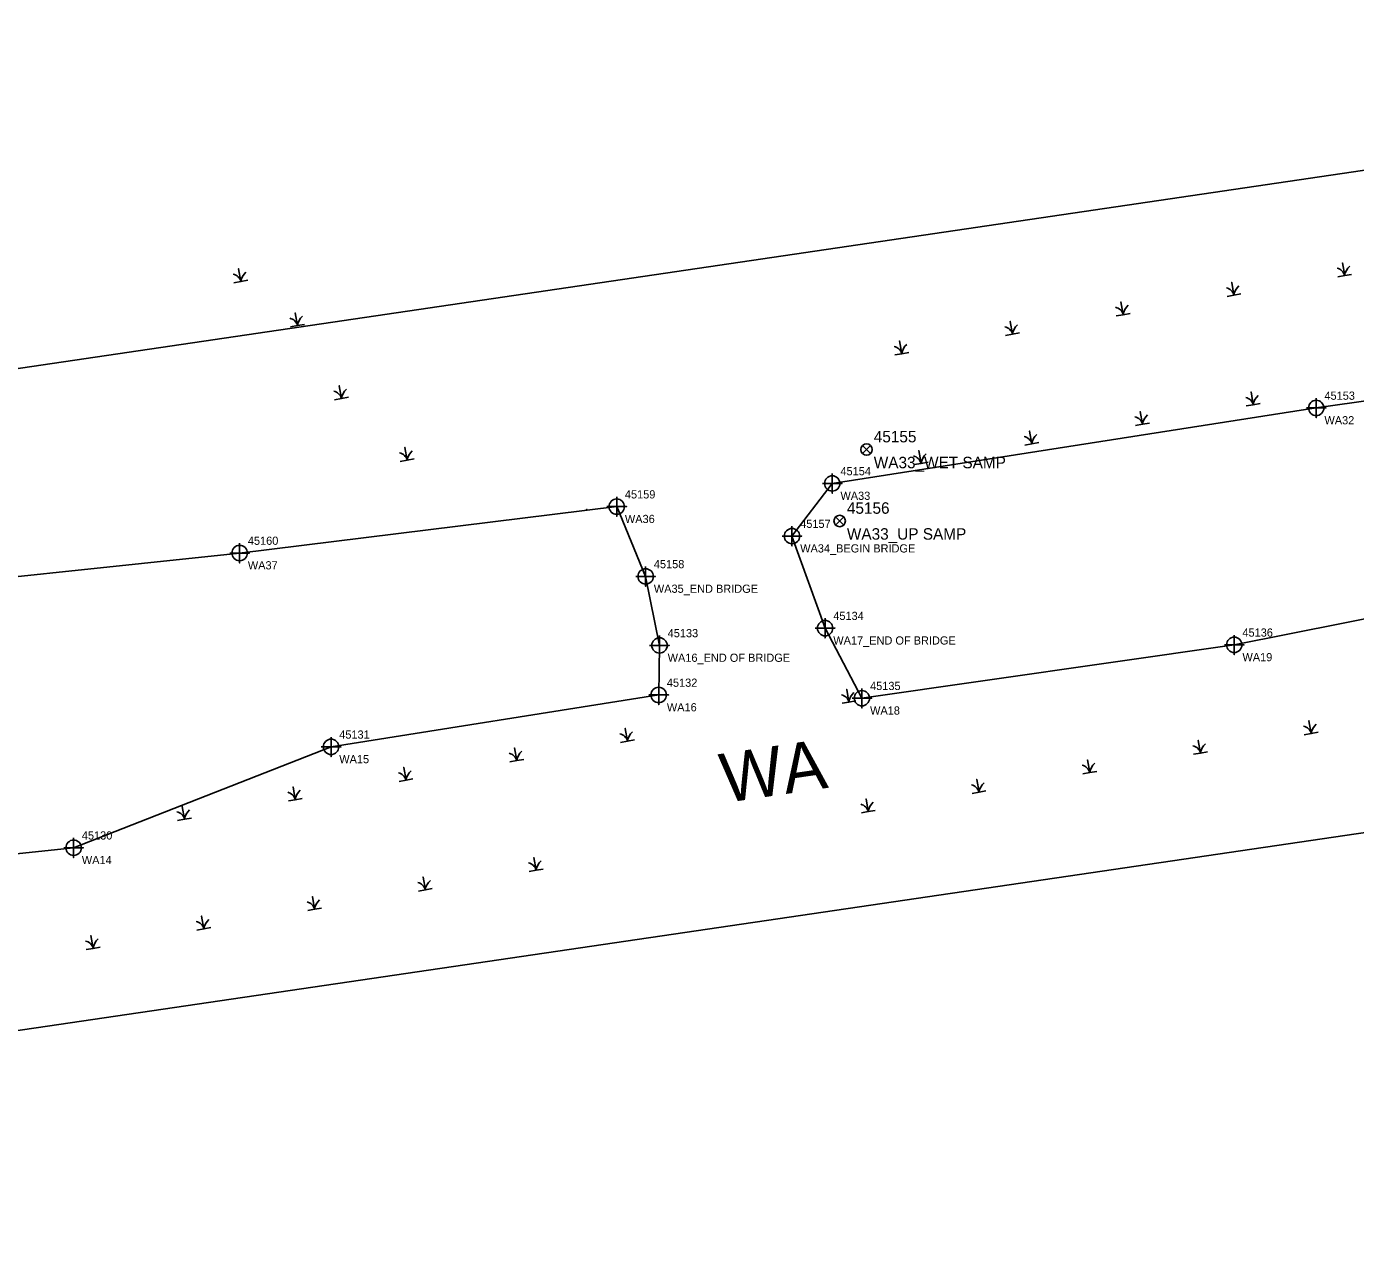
# Model space of a CAD drawing. Extents: x 2111078 to 2112659, y 581517 to 581899.
# Drawn here: x 2111863.2 to 2112268.6, y 581523.2 to 581899.2 of the extents above; entities that cross this region are included whole.
import ezdxf

# ---------------------------------------------------------------- set-up
doc = ezdxf.new("R2010")
doc.units = 0
for name, color, linetype in [('Default', 7, 'Continuous'), ('Exist Environmental Wetland Boundary', 7, 'Continuous'), ('Exist Environmental Wetland Boundary Cogo Comment', 7, 'Continuous'), ('Exist Environmental Wetland Boundary Cogo Number', 7, 'Continuous'), ('Exist Environmental Wetland Boundary Cogo Point CELL', 7, 'Continuous'), ('Exist Environmental Wetland Boundary Text', 7, 'Continuous'), ('Exist Hydro Swamp or Marsh', 7, 'Continuous')]:
    doc.layers.add(name, color=color, linetype=linetype)

msp = doc.modelspace()

# ---------------------------------------------------------------- linework, layer by layer
at = {"layer": 'Default'}
for p, q in [((2112120.71, 581771.41), (2112118.24, 581768.93)), ((2112118.24, 581771.41), (2112120.71, 581768.93)), ((2112112.51, 581749.62), (2112110.03, 581747.15)), ((2112110.03, 581749.62), (2112112.51, 581747.15))]:
    msp.add_line(p, q, dxfattribs=at)
msp.add_lwpolyline([(2111089.87, 581523.16), (2111077.52, 581722.78), (2111579.66, 581753.48), (2112568.99, 581899.18), (2112598.13, 581701.32), (2111600.4, 581554.74), (2111516.52, 581549.55)], close=True, dxfattribs=at)
for centre in [(2112119.47, 581770.17), (2112111.27, 581748.39)]:
    msp.add_circle(centre, 1.75, dxfattribs=at)
at = {"layer": 'Exist Environmental Wetland Boundary'}
for points in [[(2112579.95, 581824.73), (2112443.39, 581809.13), (2112256.64, 581782.86), (2112109, 581759.83), (2112096.72, 581743.78), (2112106.82, 581715.7), (2112118.04, 581694.33), (2112231.63, 581710.61), (2112367.17, 581737.55), (2112425.86, 581731.24), (2112435.22, 581709.75), (2112484.9, 581686.89), (2112506.03, 581692.11), (2112548.3, 581765.77), (2112570.44, 581765.42), (2112537.9, 581733.37), (2112525.65, 581690.67)], [(2111819.27, 581586.89), (2111826.15, 581643.33), (2111877.59, 581648.73), (2111956.11, 581679.5), (2112056.05, 581695.32), (2112056.3, 581710.43), (2112052.08, 581731.48), (2112043.26, 581752.76), (2111928.23, 581738.62), (2111810.46, 581726.15), (2111700.26, 581705.05), (2111584.01, 581692.46), (2111561.53, 581686.62), (2111561.94, 581674.72), (2111580.7, 581632.54), (2111595.75, 581624.66), (2111698.44, 581639.38), (2111781.79, 581581.39)]]:
    msp.add_lwpolyline(points, dxfattribs=at)
at = {"layer": 'Exist Environmental Wetland Boundary Cogo Point CELL'}
for points in [[(2112256.64, 581785.86), (2112256.64, 581779.86), (2112256.64, 581782.86), (2112259.64, 581782.86), (2112253.64, 581782.86)], [(2112109, 581762.83), (2112109, 581756.83), (2112109, 581759.83), (2112112, 581759.83), (2112106, 581759.83)], [(2112043.25, 581755.76), (2112043.25, 581749.76), (2112043.25, 581752.76), (2112046.25, 581752.76), (2112040.25, 581752.76)], [(2112096.72, 581746.78), (2112096.72, 581740.78), (2112096.72, 581743.78), (2112099.72, 581743.78), (2112093.72, 581743.78)], [(2111928.23, 581741.62), (2111928.23, 581735.62), (2111928.23, 581738.62), (2111931.23, 581738.62), (2111925.23, 581738.62)], [(2112052.08, 581734.48), (2112052.08, 581728.48), (2112052.08, 581731.48), (2112055.08, 581731.48), (2112049.08, 581731.48)], [(2112106.82, 581718.7), (2112106.82, 581712.7), (2112106.82, 581715.7), (2112109.82, 581715.7), (2112103.82, 581715.7)], [(2112056.3, 581713.43), (2112056.3, 581707.43), (2112056.3, 581710.43), (2112059.3, 581710.43), (2112053.3, 581710.43)], [(2112231.63, 581713.61), (2112231.63, 581707.61), (2112231.63, 581710.61), (2112234.63, 581710.61), (2112228.63, 581710.61)], [(2112056.05, 581698.32), (2112056.05, 581692.32), (2112056.05, 581695.32), (2112059.05, 581695.32), (2112053.05, 581695.32)], [(2112118.04, 581697.33), (2112118.04, 581691.33), (2112118.04, 581694.33), (2112121.04, 581694.33), (2112115.04, 581694.33)], [(2111956.11, 581682.5), (2111956.11, 581676.5), (2111956.11, 581679.5), (2111959.11, 581679.5), (2111953.11, 581679.5)], [(2111877.59, 581651.73), (2111877.59, 581645.73), (2111877.59, 581648.73), (2111880.59, 581648.73), (2111874.59, 581648.73)]]:
    msp.add_lwpolyline(points, dxfattribs=at)
for centre in [(2112256.64, 581782.86), (2112109, 581759.83), (2112043.25, 581752.76), (2112096.72, 581743.78), (2111928.23, 581738.62), (2112052.08, 581731.48), (2112106.82, 581715.7), (2112056.3, 581710.43), (2112231.63, 581710.61), (2112056.05, 581695.32), (2112118.04, 581694.33), (2111956.11, 581679.5), (2111877.59, 581648.73)]:
    msp.add_circle(centre, 2.34, dxfattribs=at)
at = {"layer": 'Exist Hydro Swamp or Marsh'}
for points in [[(2112263.2, 581822.85), (2112265.32, 581823.23), (2112264.63, 581827.11), (2112265.32, 581823.23), (2112267.44, 581823.6)], [(2111926.48, 581821.06), (2111928.6, 581821.43), (2111927.91, 581825.32), (2111928.6, 581821.43), (2111930.71, 581821.81)], [(2112229.42, 581816.9), (2112231.54, 581817.27), (2112230.85, 581821.16), (2112231.54, 581817.27), (2112233.66, 581817.64)], [(2112195.64, 581810.94), (2112197.76, 581811.31), (2112197.07, 581815.2), (2112197.76, 581811.31), (2112199.88, 581811.69)], [(2111943.75, 581807.59), (2111945.87, 581807.97), (2111945.19, 581811.85), (2111945.87, 581807.97), (2111947.99, 581808.34)], [(2112161.86, 581804.99), (2112163.98, 581805.36), (2112163.29, 581809.24), (2112163.98, 581805.36), (2112166.1, 581805.73)], [(2112128.08, 581799.03), (2112130.2, 581799.4), (2112129.51, 581803.29), (2112130.2, 581799.4), (2112132.32, 581799.78)], [(2111957.16, 581785.36), (2111959.27, 581785.74), (2111958.59, 581789.62), (2111959.27, 581785.74), (2111961.39, 581786.11)], [(2112235.31, 581783.47), (2112237.43, 581783.84), (2112236.75, 581787.73), (2112237.43, 581783.84), (2112239.55, 581784.21)], [(2112201.53, 581777.51), (2112203.65, 581777.89), (2112202.97, 581781.77), (2112203.65, 581777.89), (2112205.77, 581778.26)], [(2112167.76, 581771.56), (2112169.87, 581771.93), (2112169.19, 581775.81), (2112169.87, 581771.93), (2112171.99, 581772.3)], [(2111977.22, 581766.57), (2111979.33, 581766.94), (2111978.65, 581770.83), (2111979.33, 581766.94), (2111981.45, 581767.31)], [(2112133.98, 581765.6), (2112136.09, 581765.97), (2112135.41, 581769.86), (2112136.09, 581765.97), (2112138.21, 581766.35)], [(2112034.13, 581751.64), (2112034.07, 581751.99), (2112034.13, 581751.64)], [(2112111.98, 581692.78), (2112114.1, 581693.16), (2112113.42, 581697.04), (2112114.1, 581693.16), (2112116.22, 581693.53)], [(2112044.43, 581680.87), (2112046.54, 581681.25), (2112045.86, 581685.13), (2112046.54, 581681.25), (2112048.66, 581681.62)], [(2112253, 581683.18), (2112255.12, 581683.55), (2112254.43, 581687.44), (2112255.12, 581683.55), (2112257.23, 581683.93)], [(2112219.22, 581677.22), (2112221.34, 581677.6), (2112220.65, 581681.48), (2112221.34, 581677.6), (2112223.45, 581677.97)], [(2112010.65, 581674.92), (2112012.76, 581675.29), (2112012.08, 581679.17), (2112012.76, 581675.29), (2112014.88, 581675.66)], [(2111976.87, 581668.96), (2111978.98, 581669.33), (2111978.3, 581673.22), (2111978.98, 581669.33), (2111981.1, 581669.71)], [(2112185.44, 581671.27), (2112187.56, 581671.64), (2112186.87, 581675.53), (2112187.56, 581671.64), (2112189.67, 581672.01)], [(2112151.66, 581665.31), (2112153.78, 581665.68), (2112153.09, 581669.57), (2112153.78, 581665.68), (2112155.89, 581666.06)], [(2111943.09, 581663), (2111945.2, 581663.38), (2111944.52, 581667.26), (2111945.2, 581663.38), (2111947.32, 581663.75)], [(2111909.31, 581657.05), (2111911.42, 581657.42), (2111910.74, 581661.31), (2111911.42, 581657.42), (2111913.54, 581657.79)], [(2112117.88, 581659.35), (2112120, 581659.73), (2112119.31, 581663.61), (2112120, 581659.73), (2112122.11, 581660.1)], [(2112016.54, 581641.49), (2112018.66, 581641.86), (2112017.97, 581645.74), (2112018.66, 581641.86), (2112020.78, 581642.23)], [(2111982.76, 581635.53), (2111984.88, 581635.9), (2111984.19, 581639.79), (2111984.88, 581635.9), (2111987, 581636.28)], [(2111948.98, 581629.57), (2111951.1, 581629.95), (2111950.41, 581633.83), (2111951.1, 581629.95), (2111953.22, 581630.32)], [(2111915.2, 581623.62), (2111917.32, 581623.99), (2111916.63, 581627.88), (2111917.32, 581623.99), (2111919.44, 581624.36)], [(2111881.42, 581617.66), (2111883.54, 581618.03), (2111882.85, 581621.92), (2111883.54, 581618.03), (2111885.66, 581618.41)]]:
    msp.add_lwpolyline(points, dxfattribs=at)
for centre, radius, start, end in [((2111925.61, 581820.68), 3.07, 14.1403, 77.535), ((2111933.35, 581820.73), 4.81, 132.1274, 171.6222), ((2112262.34, 581822.48), 3.07, 14.1403, 77.535), ((2112270.07, 581822.53), 4.81, 132.1274, 171.6222), ((2112228.56, 581816.52), 3.07, 14.1403, 77.535), ((2112236.29, 581816.57), 4.81, 132.1274, 171.6222), ((2111950.63, 581807.27), 4.81, 132.1274, 171.6222), ((2112194.78, 581810.56), 3.07, 14.1403, 77.535), ((2112202.51, 581810.61), 4.81, 132.1274, 171.6222), ((2111942.89, 581807.22), 3.07, 14.1403, 77.535), ((2112161, 581804.61), 3.07, 14.1403, 77.535), ((2112168.73, 581804.66), 4.81, 132.1274, 171.6222), ((2112134.95, 581798.7), 4.81, 132.1274, 171.6222), ((2112127.22, 581798.65), 3.07, 14.1403, 77.535), ((2111956.29, 581784.98), 3.07, 14.1403, 77.535), ((2111964.03, 581785.04), 4.81, 132.1274, 171.6222), ((2112234.45, 581783.09), 3.07, 14.1403, 77.535), ((2112242.19, 581783.14), 4.81, 132.1274, 171.6222), ((2112200.67, 581777.13), 3.07, 14.1403, 77.535), ((2112208.41, 581777.19), 4.81, 132.1274, 171.6222), ((2112166.89, 581771.18), 3.07, 14.1403, 77.535), ((2112174.63, 581771.23), 4.81, 132.1274, 171.6222), ((2111984.09, 581766.24), 4.81, 132.1274, 171.6222), ((2111976.35, 581766.19), 3.07, 14.1403, 77.535), ((2112133.11, 581765.22), 3.07, 14.1403, 77.535), ((2112140.85, 581765.27), 4.81, 132.1274, 171.6222), ((2112111.12, 581692.41), 3.07, 14.1403, 77.535), ((2112118.86, 581692.46), 4.81, 132.1274, 171.6222), ((2112252.13, 581682.8), 3.07, 14.1403, 77.535), ((2112259.87, 581682.85), 4.81, 132.1274, 171.6222), ((2112043.56, 581680.49), 3.07, 14.1403, 77.535), ((2112051.3, 581680.54), 4.81, 132.1274, 171.6222), ((2112009.78, 581674.54), 3.07, 14.1403, 77.535), ((2112017.52, 581674.59), 4.81, 132.1274, 171.6222), ((2112218.35, 581676.85), 3.07, 14.1403, 77.535), ((2112226.09, 581676.9), 4.81, 132.1274, 171.6222), ((2112184.57, 581670.89), 3.07, 14.1403, 77.535), ((2112192.31, 581670.94), 4.81, 132.1274, 171.6222), ((2111976, 581668.58), 3.07, 14.1403, 77.535), ((2111983.74, 581668.63), 4.81, 132.1274, 171.6222), ((2112158.53, 581664.98), 4.81, 132.1274, 171.6222), ((2111942.22, 581662.63), 3.07, 14.1403, 77.535), ((2111949.96, 581662.68), 4.81, 132.1274, 171.6222), ((2112150.8, 581664.93), 3.07, 14.1403, 77.535), ((2111916.18, 581656.72), 4.81, 132.1274, 171.6222), ((2112117.02, 581658.98), 3.07, 14.1403, 77.535), ((2112124.75, 581659.03), 4.81, 132.1274, 171.6222), ((2111908.44, 581656.67), 3.07, 14.1403, 77.535), ((2112015.68, 581641.11), 3.07, 14.1403, 77.535), ((2112023.41, 581641.16), 4.81, 132.1274, 171.6222), ((2111981.9, 581635.15), 3.07, 14.1403, 77.535), ((2111989.63, 581635.2), 4.81, 132.1274, 171.6222), ((2111948.12, 581629.2), 3.07, 14.1403, 77.535), ((2111955.85, 581629.25), 4.81, 132.1274, 171.6222), ((2111914.34, 581623.24), 3.07, 14.1403, 77.535), ((2111922.07, 581623.29), 4.81, 132.1274, 171.6222), ((2111880.56, 581617.28), 3.07, 14.1403, 77.535), ((2111888.29, 581617.33), 4.81, 132.1274, 171.6222)]:
    msp.add_arc(centre, radius, start, end, dxfattribs=at)

# ---------------------------------------------------------------- texts
at = {"layer": 'Default'}
for s, p in [('45155', (2112121.67, 581772.37)), ('WA33_WET SAMP', (2112121.67, 581764.47)), ('45156', (2112113.47, 581750.59)), ('WA33_UP SAMP', (2112113.47, 581742.69))]:
    msp.add_text(s, height=3.5, dxfattribs=at).set_placement(p)
at = {"layer": 'Exist Environmental Wetland Boundary Cogo Comment'}
for s, p in [('WA32', (2112259.14, 581777.86)), ('WA33', (2112111.5, 581754.83)), ('WA36', (2112045.75, 581747.76)), ('WA34_BEGIN BRIDGE', (2112099.22, 581738.78)), ('WA37', (2111930.73, 581733.62)), ('WA35_END BRIDGE', (2112054.58, 581726.48)), ('WA17_END OF BRIDGE', (2112109.32, 581710.7)), ('WA16_END OF BRIDGE', (2112058.8, 581705.43)), ('WA19', (2112234.13, 581705.61)), ('WA16', (2112058.55, 581690.32)), ('WA18', (2112120.54, 581689.33)), ('WA15', (2111958.61, 581674.5)), ('WA14', (2111880.09, 581643.73))]:
    msp.add_text(s, height=2.5, dxfattribs=at).set_placement(p)
at = {"layer": 'Exist Environmental Wetland Boundary Cogo Number'}
for s, p in [('45153', (2112259.14, 581785.36)), ('45154', (2112111.5, 581762.33)), ('45159', (2112045.75, 581755.26)), ('45157', (2112099.22, 581746.28)), ('45160', (2111930.73, 581741.12)), ('45158', (2112054.58, 581733.98)), ('45134', (2112109.32, 581718.2)), ('45133', (2112058.8, 581712.93)), ('45136', (2112234.13, 581713.11)), ('45132', (2112058.55, 581697.82)), ('45135', (2112120.54, 581696.83)), ('45131', (2111958.61, 581682)), ('45130', (2111880.09, 581651.23))]:
    msp.add_text(s, height=2.5, dxfattribs=at).set_placement(p)
at = {"layer": 'Exist Environmental Wetland Boundary Text'}
msp.add_text('WA', height=15, rotation=8.3579, dxfattribs=at).set_placement((2112076.08, 581662.36))

doc.saveas('drawing.dxf')
